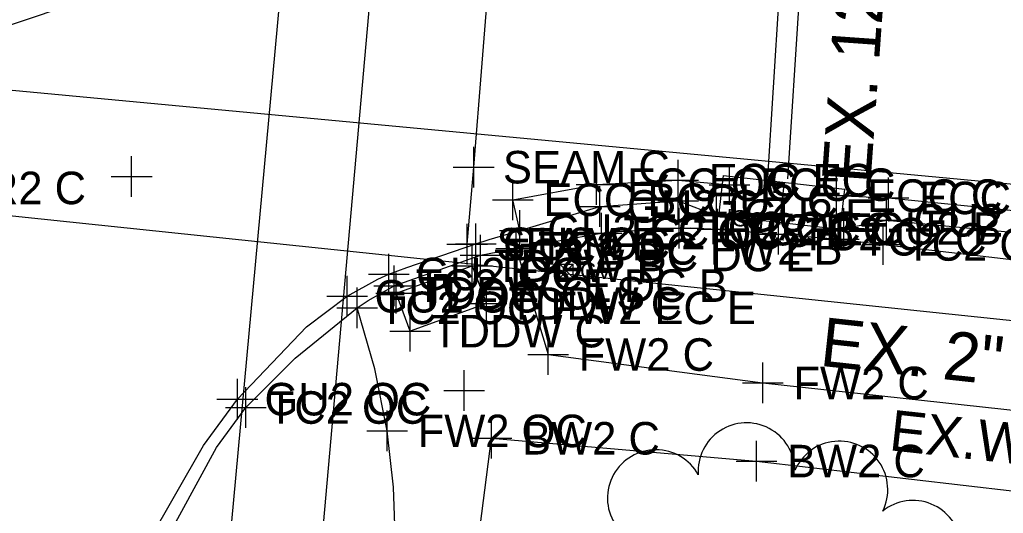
# Model space of a CAD drawing. Extents: x 1363693 to 1365209, y 422201 to 424153.
# Drawn here: x 1364280.58 to 1364328.95, y 423421.9 to 423446.19 of the extents above; entities that cross this region are included whole.
import ezdxf

# ---------------------------------------------------------------- set-up
doc = ezdxf.new("R2010")
doc.units = 0
for name, color, linetype in [('BASELINE-CL-RW', 7, 'Continuous'), ('DR_X_Cells', 7, 'Continuous'), ('DR_X_Storm_Sewer', 7, 'Continuous'), ('DR_X_Text', 7, 'Continuous'), ('O-ALGN-TEXT-BASELINE-WERK-CL-RW', 7, 'Continuous'), ('OWNERS', 7, 'Continuous'), ('PV_X_Driveway', 7, 'Continuous'), ('RD_X_Misc_Items', 7, 'Continuous'), ('RD_X_Text', 7, 'Continuous'), ('SV_X_Original_Ground', 7, 'Continuous'), ('SV_X_Shot_Marker', 7, 'Continuous'), ('UT_X_Gas', 7, 'Continuous'), ('UT_X_Gas_Cells', 7, 'Continuous'), ('UT_X_Gas_Text', 7, 'Continuous'), ('UT_X_Sanitary_Line', 7, 'Continuous'), ('UT_X_Telecom', 7, 'Continuous'), ('UT_X_Water', 7, 'Continuous'), ('VG_X_Cells', 7, 'Continuous')]:
    doc.layers.add(name, color=color, linetype=linetype)

msp = doc.modelspace()

# ---------------------------------------------------------------- linework, layer by layer
at = {"layer": 'BASELINE-CL-RW'}
msp.add_line((1364298.991, 423433.102), (1364303.244, 423434.612), dxfattribs=at)
msp.add_line((1364298.991, 423433.102), (1364303.244, 423434.612), dxfattribs=at)
for points in [[(1364303.244, 423434.612), (1364304.517, 423434.849), (1364304.517, 423434.849), (1364304.996, 423434.937), (1364304.996, 423434.937), (1364308.594, 423435.589), (1364308.594, 423435.589), (1364309.187, 423435.695), (1364309.187, 423435.695), (1364309.714, 423435.758), (1364309.714, 423435.758), (1364313.015, 423435.939), (1364313.015, 423435.939), (1364313.561, 423435.944), (1364313.561, 423435.944), (1364314.902, 423435.884), (1364314.902, 423435.884), (1364317.889, 423435.642), (1364320.868, 423435.385), (1364323.046, 423435.131), (1364342.139, 423432.905), (1364364.042, 423430.585)], [(1364284.317, 423396.624), (1364284.452, 423398.343), (1364284.881, 423402.739), (1364285.303, 423405.828), (1364285.63, 423408.793), (1364285.905, 423411.824), (1364286.041, 423414.032), (1364286.739, 423417.927), (1364286.739, 423417.927), (1364287.559, 423420.171), (1364287.559, 423420.171), (1364290.267, 423425.145), (1364290.267, 423425.145), (1364291.708, 423427.107), (1364291.708, 423427.107), (1364294.123, 423429.532), (1364294.123, 423429.532), (1364297.169, 423432.011), (1364297.169, 423432.011), (1364297.72, 423432.378), (1364297.72, 423432.378), (1364298.991, 423433.102), (1364298.991, 423433.102)]]:
    msp.add_lwpolyline(points, dxfattribs=at)
at = {"layer": 'DR_X_Cells'}
for p, q in [((1364314.965, 423436.538), (1364315.189, 423438.525)), ((1364315.189, 423438.525), (1364321.151, 423437.853)), ((1364318.17, 423438.189), (1364317.946, 423436.202)), ((1364320.927, 423435.866), (1364321.151, 423437.853)), ((1364320.927, 423435.866), (1364314.965, 423436.538))]:
    msp.add_line(p, q, dxfattribs=at)
at = {"layer": 'DR_X_Storm_Sewer'}
for p, q in [((1364270.979, 423442.857), (1364316.538, 423458.209)), ((1364318.608, 423458.378), (1364317.345, 423438.42)), ((1364319.606, 423458.315), (1364318.343, 423438.357))]:
    msp.add_line(p, q, dxfattribs=at)
at = {"layer": 'O-ALGN-TEXT-BASELINE-WERK-CL-RW'}
for points in [[(1364304.996, 423434.937), (1364306.567, 423429.714), (1364317.126, 423428.316), (1364342.635, 423425.528), (1364362.002, 423423.374)], [(1364277.041, 423186.453), (1364279.249, 423211.34), (1364281.062, 423228.074), (1364281.809, 423236.125), (1364283.024, 423250.18), (1364284.121, 423261.072), (1364286.393, 423285.925), (1364288.893, 423310.853), (1364289.461, 423315.932), (1364291.285, 423335.668), (1364291.825, 423341.593), (1364293.598, 423360.72), (1364295.788, 423384.44), (1364295.973, 423385.791), (1364296.712, 423394.509), (1364298.068, 423410.324), (1364299.056, 423420.392), (1364298.963, 423423.182), (1364298.651, 423425.956), (1364298.651, 423425.956), (1364298.044, 423429.016), (1364297.169, 423432.011), (1364297.169, 423432.011)], [(1364288.049, 423260.634), (1364290.333, 423285.623), (1364291.2, 423296.798), (1364291.58, 423300.813), (1364292.823, 423310.443), (1364293.111, 423313.713), (1364294.382, 423326.121), (1364294.901, 423331.286), (1364295.277, 423335.321), (1364295.682, 423341.235), (1364297.432, 423360.37), (1364299.6, 423383.973), (1364299.789, 423385.241), (1364300.506, 423393.275), (1364302.133, 423410.038), (1364303.056, 423419.974), (1364303.785, 423425.594), (1364316.813, 423424.472), (1364342.217, 423421.511), (1364361.421, 423419.342)]]:
    msp.add_lwpolyline(points, dxfattribs=at)
at = {"layer": 'OWNERS'}
for points in [[(1364302.59, 423435.143), (1364302.905, 423438.934), (1364303.728, 423449.188), (1364304.715, 423460.091), (1364305.13, 423463.692)], [(1364305.181, 423435.811), (1364304.834, 423437.332), (1364308.946, 423438.074), (1364308.946, 423438.074), (1364312.957, 423438.298), (1364312.957, 423438.298), (1364315.488, 423438.073)], [(1364286.897, 423420.483), (1364289.614, 423425.237), (1364289.614, 423425.237), (1364291.284, 423427.518), (1364291.284, 423427.518), (1364294.679, 423431.074), (1364294.679, 423431.074), (1364296.69, 423432.581), (1364296.69, 423432.581), (1364298.189, 423433.425), (1364298.189, 423433.425), (1364298.732, 423433.675), (1364298.732, 423433.675), (1364299.624, 423434.004), (1364299.624, 423434.004), (1364303.019, 423435.162), (1364303.019, 423435.162), (1364303.673, 423435.37), (1364303.673, 423435.37), (1364305.181, 423435.811), (1364305.181, 423435.811), (1364309.108, 423437.002), (1364312.961, 423437.272), (1364314.841, 423436.552)], [(1364320.743, 423437.535), (1364323.31, 423437.421), (1364342.401, 423435.494), (1364364.277, 423433.104)], [(1364321.108, 423435.914), (1364323.207, 423436.321), (1364342.334, 423434.491), (1364364.114, 423432.362)]]:
    msp.add_lwpolyline(points, dxfattribs=at)
at = {"layer": 'PV_X_Driveway'}
for points in [[(1364320.743, 423437.535), (1364323.31, 423437.421), (1364342.401, 423435.494), (1364364.277, 423433.104)], [(1364321.108, 423435.914), (1364323.207, 423436.321), (1364342.334, 423434.491), (1364364.114, 423432.362)]]:
    msp.add_lwpolyline(points, dxfattribs=at)
at = {"layer": 'RD_X_Misc_Items'}
for p, q in [((1364299.098, 423432.732), (1364302.832, 423434.081)), ((1364299.098, 423432.732), (1364302.832, 423434.081)), ((1364302.832, 423434.081), (1364303.535, 423432.227)), ((1364302.832, 423434.081), (1364303.535, 423432.227)), ((1364299.784, 423430.865), (1364299.098, 423432.732)), ((1364299.784, 423430.865), (1364299.098, 423432.732)), ((1364303.535, 423432.227), (1364299.784, 423430.865)), ((1364303.535, 423432.227), (1364299.784, 423430.865))]:
    msp.add_line(p, q, dxfattribs=at)
at = {"layer": 'SV_X_Original_Ground'}
for p, q in [((1364302.905, 423437.934), (1364302.905, 423439.934)), ((1364286.088, 423437.468), (1364286.088, 423439.468)), ((1364301.905, 423438.934), (1364303.905, 423438.934)), ((1364285.088, 423438.468), (1364287.088, 423438.468)), ((1364302.59, 423434.143), (1364302.59, 423436.143)), ((1364301.59, 423435.143), (1364303.59, 423435.143)), ((1364302.832, 423433.081), (1364302.832, 423435.081)), ((1364301.832, 423434.081), (1364303.832, 423434.081)), ((1364299.098, 423431.732), (1364299.098, 423433.732)), ((1364303.535, 423431.227), (1364303.535, 423433.227)), ((1364298.098, 423432.732), (1364300.098, 423432.732)), ((1364302.535, 423432.227), (1364304.535, 423432.227)), ((1364299.784, 423429.865), (1364299.784, 423431.865)), ((1364298.784, 423430.865), (1364300.784, 423430.865)), ((1364302.434, 423426.952), (1364302.434, 423428.952)), ((1364301.434, 423427.952), (1364303.434, 423427.952))]:
    msp.add_line(p, q, dxfattribs=at)
at = {"layer": 'SV_X_Shot_Marker'}
for p, q in [((1364312.957, 423437.298), (1364312.957, 423439.298)), ((1364308.946, 423437.074), (1364308.946, 423439.074)), ((1364315.488, 423437.073), (1364315.488, 423439.073)), ((1364304.834, 423436.332), (1364304.834, 423438.332)), ((1364311.957, 423438.298), (1364313.957, 423438.298)), ((1364312.961, 423436.272), (1364312.961, 423438.272)), ((1364320.743, 423436.535), (1364320.743, 423438.535)), ((1364323.31, 423436.421), (1364323.31, 423438.421)), ((1364307.946, 423438.074), (1364309.946, 423438.074)), ((1364309.108, 423436.002), (1364309.108, 423438.002)), ((1364314.488, 423438.073), (1364316.488, 423438.073)), ((1364303.834, 423437.332), (1364305.834, 423437.332)), ((1364311.961, 423437.272), (1364313.961, 423437.272)), ((1364314.841, 423435.552), (1364314.841, 423437.552)), ((1364319.743, 423437.535), (1364321.743, 423437.535)), ((1364322.31, 423437.421), (1364324.31, 423437.421)), ((1364323.207, 423435.321), (1364323.207, 423437.321)), ((1364305.181, 423434.811), (1364305.181, 423436.811)), ((1364308.108, 423437.002), (1364310.108, 423437.002)), ((1364313.015, 423434.939), (1364313.015, 423436.939)), ((1364314.902, 423434.884), (1364314.902, 423436.884)), ((1364321.108, 423434.914), (1364321.108, 423436.914)), ((1364309.187, 423434.695), (1364309.187, 423436.695)), ((1364313.841, 423436.552), (1364315.841, 423436.552)), ((1364317.889, 423434.642), (1364317.889, 423436.642)), ((1364320.868, 423434.385), (1364320.868, 423436.385)), ((1364322.207, 423436.321), (1364324.207, 423436.321)), ((1364303.019, 423434.162), (1364303.019, 423436.162)), ((1364304.181, 423435.811), (1364306.181, 423435.811)), ((1364304.996, 423433.937), (1364304.996, 423435.937)), ((1364312.015, 423435.939), (1364314.015, 423435.939)), ((1364313.902, 423435.884), (1364315.902, 423435.884)), ((1364320.108, 423435.914), (1364322.108, 423435.914)), ((1364323.046, 423434.131), (1364323.046, 423436.131)), ((1364303.244, 423433.612), (1364303.244, 423435.612)), ((1364308.187, 423435.695), (1364310.187, 423435.695)), ((1364316.889, 423435.642), (1364318.889, 423435.642)), ((1364319.868, 423435.385), (1364321.868, 423435.385)), ((1364302.019, 423435.162), (1364304.019, 423435.162)), ((1364303.996, 423434.937), (1364305.996, 423434.937)), ((1364322.046, 423435.131), (1364324.046, 423435.131)), ((1364298.732, 423432.675), (1364298.732, 423434.675)), ((1364302.244, 423434.612), (1364304.244, 423434.612)), ((1364298.991, 423432.102), (1364298.991, 423434.102)), ((1364296.69, 423431.581), (1364296.69, 423433.581)), ((1364297.732, 423433.675), (1364299.732, 423433.675)), ((1364297.169, 423431.011), (1364297.169, 423433.011)), ((1364297.991, 423433.102), (1364299.991, 423433.102)), ((1364295.69, 423432.581), (1364297.69, 423432.581)), ((1364296.169, 423432.011), (1364298.169, 423432.011)), ((1364306.567, 423428.714), (1364306.567, 423430.714)), ((1364305.567, 423429.714), (1364307.567, 423429.714)), ((1364317.126, 423427.316), (1364317.126, 423429.316)), ((1364291.284, 423426.518), (1364291.284, 423428.518)), ((1364291.708, 423426.107), (1364291.708, 423428.107)), ((1364316.126, 423428.316), (1364318.126, 423428.316)), ((1364290.284, 423427.518), (1364292.284, 423427.518)), ((1364290.708, 423427.107), (1364292.708, 423427.107)), ((1364298.651, 423424.956), (1364298.651, 423426.956)), ((1364303.785, 423424.594), (1364303.785, 423426.594)), ((1364297.651, 423425.956), (1364299.651, 423425.956)), ((1364302.785, 423425.594), (1364304.785, 423425.594)), ((1364316.813, 423423.472), (1364316.813, 423425.472)), ((1364315.813, 423424.472), (1364317.813, 423424.472))]:
    msp.add_line(p, q, dxfattribs=at)
at = {"layer": 'UT_X_Gas'}
msp.add_lwpolyline([(1364225.475, 423227.676), (1364230.287, 423271.655), (1364244.946, 423427.254), (1364255.626, 423426.642), (1364257.028, 423438.97), (1364362.136, 423427.961)], dxfattribs=at)
at = {"layer": 'UT_X_Gas_Cells'}
for p, q in [((1364307.138, 423433.495), (1364307.803, 423434.16)), ((1364307.138, 423434.16), (1364307.803, 423433.495)), ((1364307.138, 423434.16), (1364307.803, 423434.16)), ((1364307.138, 423433.495), (1364307.138, 423434.16)), ((1364307.803, 423433.495), (1364307.803, 423434.16)), ((1364307.138, 423433.495), (1364307.803, 423433.495))]:
    msp.add_line(p, q, dxfattribs=at)
at = {"layer": 'UT_X_Sanitary_Line'}
msp.add_lwpolyline([(1364253.212, 423263.577), (1364270.768, 423443.607), (1364363.352, 423434.92)], dxfattribs=at)
at = {"layer": 'UT_X_Telecom'}
msp.add_lwpolyline([(1364331.133, 423132.499), (1364271.573, 423151.567), (1364307.701, 423558.666)], dxfattribs=at)
at = {"layer": 'UT_X_Water'}
msp.add_lwpolyline([(1364264.276, 423134.188), (1364290.904, 423420.252), (1364296.496, 423480.942), (1364304.106, 423560.043)], dxfattribs=at)
at = {"layer": 'VG_X_Cells'}
for centre, start, end in [((1364316.323, 423423.973), 1.241, 184.1237), ((1364320.886, 423423.072), 333.5487, 156.4314), ((1364311.865, 423422.65), 28.9333, 211.816), ((1364324.507, 423420.155), 305.8564, 128.7391)]:
    msp.add_arc(centre, 2.381, start, end, dxfattribs=at)

# ---------------------------------------------------------------- texts
at = {"layer": 'DR_X_Text'}
for s, height, rotation, p in [('EX. 12" STM.', 2.4, 85.9578, (1364322.414, 423438.088)), ('DGI', 0.8, 173.5687, (1364317.246, 423436.683))]:
    msp.add_text(s, height=height, rotation=rotation, dxfattribs=at).set_placement(p)
at = {"layer": 'RD_X_Text'}
msp.add_text('EX.WALK', height=2, rotation=353.7177, dxfattribs=at).set_placement((1364323.292, 423425.012))
at = {"layer": 'SV_X_Original_Ground'}
for s, p in [('SEAM C', (1364304.344, 423438.134)), ('CR2 C', (1364277.425, 423437.113)), ('SEAM B', (1364304.029, 423434.343)), ('TDDW B', (1364303.903, 423433.281)), ('TDDW CLS', (1364300.169, 423431.932)), ('TDDW C', (1364304.606, 423431.427)), ('TDDW C', (1364300.855, 423430.065))]:
    msp.add_text(s, height=1.6, dxfattribs=at).set_placement(p)
at = {"layer": 'SV_X_Shot_Marker'}
for s, p in [('ECC OC', (1364310.446, 423437.274)), ('ECC EC', (1364314.457, 423437.498)), ('ECC C', (1364316.988, 423437.273)), ('ECC C', (1364322.243, 423436.735)), ('ECC C', (1364324.81, 423436.621)), ('ECC BC', (1364306.334, 423436.532)), ('GU2 C', (1364310.445, 423436.202)), ('GU2 C', (1364314.298, 423436.472)), ('GU2 E', (1364316.178, 423435.752)), ('TC2 OC', (1364314.086, 423435.139)), ('GU2 C', (1364324.544, 423435.521)), ('GU2 EC ECC B', (1364306.518, 423435.011)), ('TC2 OC', (1364310.258, 423434.895)), ('TC2 EC', (1364315.973, 423435.084)), ('TC2 C', (1364318.96, 423434.842)), ('GU2 B', (1364322.445, 423435.114)), ('GU2 OC', (1364304.356, 423434.362)), ('TC2 C', (1364321.939, 423434.585)), ('TC2 C', (1364324.117, 423434.331)), ('TC2 B BC DC E', (1364304.315, 423433.812)), ('TC2 OC FW2 B', (1364306.067, 423434.137)), ('GU2 OC', (1364300.069, 423432.875)), ('TC2 EC E DC B', (1364300.062, 423432.302)), ('GU2 OC', (1364298.027, 423431.781)), ('TC2 OC FW2 EC E', (1364298.24, 423431.211)), ('FW2 C', (1364308.067, 423428.914)), ('FW2 C', (1364318.626, 423427.516)), ('GU2 OC', (1364292.621, 423426.718)), ('TC2 OC', (1364292.779, 423426.307)), ('FW2 OC', (1364300.151, 423425.156)), ('BW2 C', (1364305.285, 423424.794)), ('BW2 C', (1364318.313, 423423.672))]:
    msp.add_text(s, height=1.6, dxfattribs=at).set_placement(p)
at = {"layer": 'UT_X_Gas_Text'}
msp.add_text('GV', height=0.8, dxfattribs=at).set_placement((1364308.139, 423433.428))
msp.add_text('EX. 2" GM', height=2.4, rotation=353.8091, dxfattribs=at).set_placement((1364319.879, 423429.167))

doc.saveas('drawing.dxf')
